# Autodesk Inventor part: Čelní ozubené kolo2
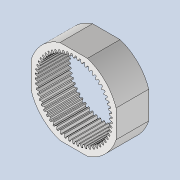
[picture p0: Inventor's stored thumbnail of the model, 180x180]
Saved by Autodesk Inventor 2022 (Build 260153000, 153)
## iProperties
CustomPartVersion: 1
Created: 2025-05
Part Number: Čelní ozubené kolo2
Material: Všeobecné
Document SubType Name: Modeling
Designer: jbart
Categories: <?xml version="1.0" encoding="UTF-16"?> <MemberInstance><Categories><FamilyTemplate><FamilyTemplateParameter ValueType="xs:double" Id="1" ObjectReferenceKey="da
Density: 1 g/cm^3
Appearance: Výchozí
Mass: 5618.58 g
Surface Area: 5954.78 cm^2
Volume: 5618.58 cm^3
Author: jbart
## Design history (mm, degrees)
sketch "Sketch1"
  geometry: C1 r 205 at (0, 0)
  constraints: 1 centre point
  dimensions: "d0" = 410 diameter of C1
extrude "Extrusion1" new body sketch "Sketch1" distance "d1" = 150 (= da_b); taper "d2" = 0 deg
workplane "Work Plane2"
sketch "Sketch2"
  geometry: C1 r 205 at (0, 0) reference; C2 r 171 at (0, 0)
  constraints: 1 centre point, 1 coincident
  dimensions: "d3" = 342 diameter of C2 (= da_d)
feature "Roztečný průměr" sketch "Sketch2" dims "d4" = 10, "d5" = 0
workplane "Work Plane8"
workplane "Work Plane9"
feature "Čelní ozubené kolo" dims "da_b" = 150, "da_d" = 342, "da_z" = 570, "da_aw" = 107.36314, "da_da" = 329.75677, "da_df" = 355.75525, "da_dw" = 339.98329, "da_z2" = 210, "da_beta" = 0, "da_lefttooth" = 0, "da_righttooth" = 0, "da_straighttooth" = 10
sketch "Náčrt5"
  geometry: L1 (0, 0)-(0, 50); L2 (-150, 215)-(150, 215); L3 (150, 215)-(150, 195); L4 (150, 195)-(-150, 195); L5 (-150, 195)-(-150, 215)
  constraints: 10 end point, 2 parallel, 1 horizontal, 1 perpendicular, 1 vertical, 1 other
  dimensions: "d60" = 50 distance of L1.start L1.end; "d61" = 300 distance of L3.end L4.end; "d62" = 20 distance of L2.end L3.end; "d63" = 195 distance from line of L1.start L4
extrude "Vysunutí3" cut sketch "Náčrt5" extent not by distance; stored distance "d64" = 0; taper "d65" = 0 deg
pattern_circular "Kruhové pole2" dims angle "d67" = 360 deg
body "Solid1"
body "Srf1"
other parameters: "d16" = 107.36314 (= da_aw), "d17" = 0, "d34" = 0.55116 (computed from da_z), "d39" = 0, "d45" = 0, "d47" = 107.36314 (= da_aw), "d50" = 0, "d51" = 0, "d52" = 107.36314 (= da_aw)
